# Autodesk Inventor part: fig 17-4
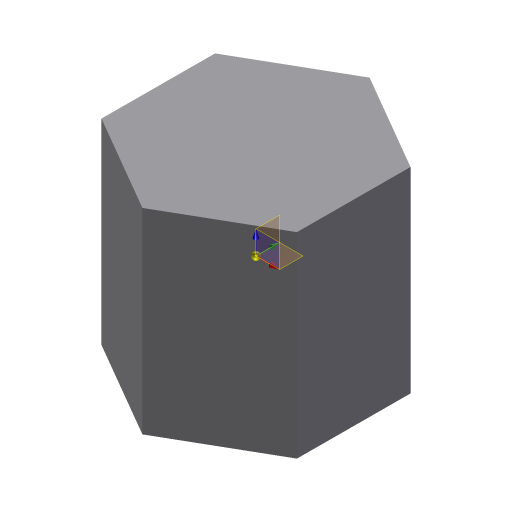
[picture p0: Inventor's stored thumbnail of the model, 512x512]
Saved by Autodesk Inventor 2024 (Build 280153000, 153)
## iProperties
Created: 2008-06
Part Number: fig 17-4
Document SubType Name: Modeling
Designer: CADCIM
Mass: 866.025 g
Surface Area: 519.615 cm^2
Volume: 866.025 cm^3
Density: 1 g/cm^3
Material: Generic
Appearance: Default
Author: CADCIM
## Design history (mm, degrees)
sketch "Sketch1"
  geometry: L1 (0.184, 57.735)-(50.092, 28.708); L2 (50.092, 28.708)-(49.908, -29.027); L3 (49.908, -29.027)-(-0.184, -57.735); L4 (-0.184, -57.735)-(-50.092, -28.708); L5 (-50.092, -28.708)-(-49.908, 29.027); L6 (-49.908, 29.027)-(0.184, 57.735); 1 further point
  constraints: 12 end point, 13 other
  dimensions: "d0" = 100 distance between parallel lines of L2 L5
extrude "Extrusion1" new body sketch "Sketch1" distance "d1" = 100; taper "d2" = 0 deg
body "Solid1"
